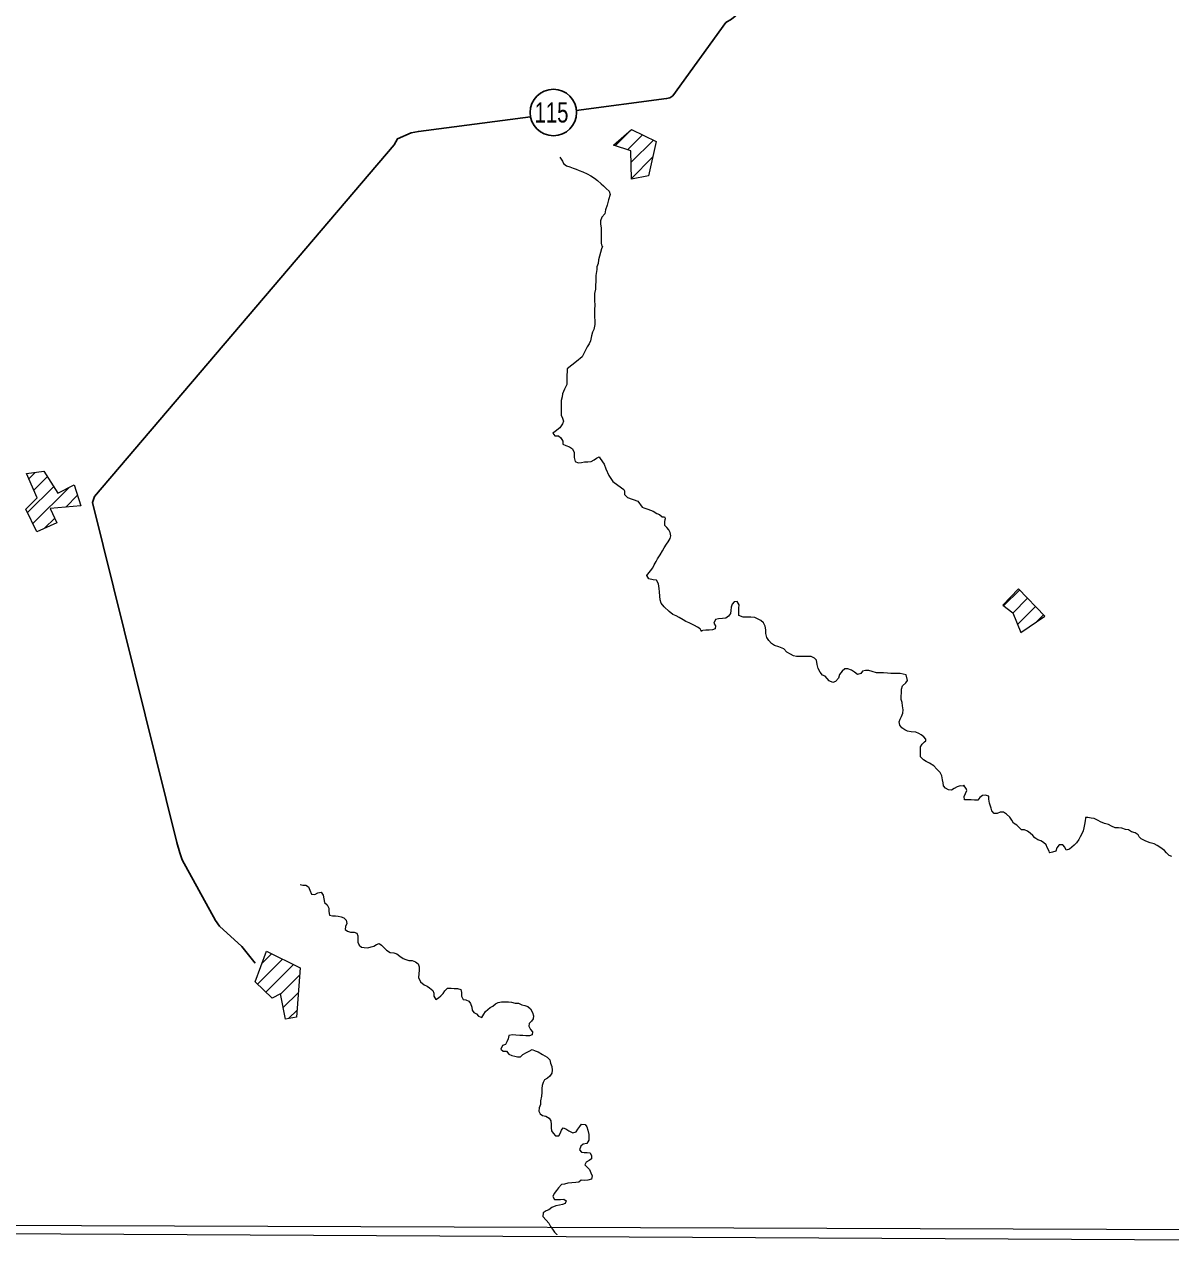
# Model space of a CAD drawing. Extents: x 553962 to 842807, y 8883888 to 9032388.
# Drawn here: x 611216 to 615180, y 8898711 to 8902976 of the extents above; entities that cross this region are included whole.
import ezdxf
from ezdxf.enums import TextEntityAlignment as Align

# ---------------------------------------------------------------- set-up
doc = ezdxf.new("R2010")
doc.units = 0
doc.header["$LTSCALE"] = 200
doc.layers.add('6', color=7, linetype='Continuous', lineweight=13)

msp = doc.modelspace()

# ---------------------------------------------------------------- linework, layer by layer
at = {"layer": '6'}
for p, q in [((613258.9, 8902557.5), (613307.3, 8902605.9)), ((613301.4, 8902543.4), (613353.5, 8902595.5)), ((613314.5, 8902500), (613391.6, 8902577)), ((613315.6, 8902444.5), (613388.7, 8902517.5)), ((611230.3, 8901404.8), (611252.2, 8901426.7)), ((611226.5, 8901287.9), (611316.8, 8901378.2)), ((611248, 8901365.9), (611294.8, 8901412.8)), ((611245.1, 8901249.9), (611370.1, 8901374.9)), ((611358.8, 8901307.1), (611399.5, 8901347.8)), ((611285.4, 8901233.7), (611320.5, 8901268.7)), ((614602.7, 8900965), (614658.4, 8901020.7)), ((614634.6, 8900940.2), (614686, 8900991.7)), ((614651.2, 8900900.4), (614713.6, 8900962.7)), ((614718.1, 8900910.6), (614741.2, 8900933.8)), ((613558.2, 8900878.2), (613557.9, 8900877)), ((612037, 8899727.6), (612070.7, 8899761.3)), ((612022, 8899656), (612108.6, 8899742.6)), ((612051.1, 8899628.6), (612146.6, 8899724)), ((612101.1, 8899622), (612167.9, 8899688.8)), ((612110.5, 8899574.8), (612163.2, 8899627.5)), ((612129.1, 8899536.8), (612158.5, 8899566.2))]:
    msp.add_line(p, q, dxfattribs=at)
for points in [[(618535.2, 8909853.3), (607574.3, 8909890.7), (607543.3, 8898835.3), (618504.2, 8898795.8)], [(613253.6, 8902559.2), (613316.1, 8902613.6), (613400.9, 8902572.5), (613374.3, 8902452.9), (613315.7, 8902442), (613313.8, 8902539.4)], [(611222.2, 8901422.7), (611283.2, 8901431), (611331.4, 8901355.2), (611388, 8901384.1), (611411, 8901311.7), (611304.4, 8901302.2), (611328.1, 8901252.8), (611258.8, 8901221.7), (611220.8, 8901299.8), (611260, 8901339.5)], [(614654.9, 8901024.3), (614599.9, 8900967.2), (614634.5, 8900940.5), (614662.7, 8900873), (614745.5, 8900929.3)], [(612052.6, 8899770.2), (612169.7, 8899712.7), (612156.6, 8899541.5), (612118.4, 8899535), (612101, 8899622.7), (612072.7, 8899608.2), (612013.7, 8899663.8)]]:
    msp.add_lwpolyline(points, close=True, dxfattribs=at)
at = {"layer": '6', "lineweight": 25}
for points in [[(614884.3, 8904031.6), (614289.5, 8903510.2), (613661, 8902994.8), (613641.6, 8902983.7), (613458.3, 8902730.3), (613448.1, 8902723.2), (613436.9, 8902720.2), (613124.7, 8902678.9)], [(612965.8, 8902657.9), (612578.6, 8902606.6), (612553.1, 8902601.6), (612506.2, 8902581.3), (612494.9, 8902560.9), (611458.3, 8901343.3), (611451.1, 8901322.9), (611742.2, 8900146.7), (611753.3, 8900110), (611761.3, 8900086.6), (611876.7, 8899876.5), (611889.9, 8899857.1), (611968.1, 8899786.6), (612014.2, 8899728.6)]]:
    msp.add_lwpolyline(points, dxfattribs=at)
at = {"layer": '6'}
for points in [[(613067.8, 8902517.8), (613076.8, 8902504.5), (613080.8, 8902495.3), (613091, 8902488.1), (613102.1, 8902483.9), (613113.3, 8902479.8), (613124.5, 8902476.7), (613134.6, 8902471.5), (613147.8, 8902467.4), (613162, 8902460.2), (613175.2, 8902452.9), (613187.3, 8902444.7), (613197.4, 8902436.5), (613210.6, 8902425.2), (613218.7, 8902418.1), (613227.7, 8902409.8), (613238.9, 8902399.6), (613241.8, 8902388.4), (613236.6, 8902370.1), (613231.4, 8902351.8), (613226.2, 8902335.5), (613223.1, 8902321.3), (613212.8, 8902310.1), (613208.7, 8902296.9), (613208.6, 8902286.7), (613210.5, 8902272.5), (613210.5, 8902262.3), (613210.3, 8902245), (613210.2, 8902232.7), (613210.2, 8902220.5), (613213.1, 8902210.3), (613215.1, 8902208.5)], [(613214.9, 8902208.8), (613211.4, 8902200.8), (613205.1, 8902175.3), (613200.9, 8902162.1), (613199.8, 8902149.9), (613195.7, 8902138.7), (613195.6, 8902128.6), (613192.4, 8902108.2), (613192.3, 8902087.8), (613191.2, 8902074.6), (613191.1, 8902061.3), (613187.9, 8902046.1), (613187.8, 8902034.9), (613187.8, 8902023.7), (613188.9, 8902003.7), (613187.6, 8901993.1), (613187.5, 8901980.9), (613187.4, 8901965.6), (613188.3, 8901951.4), (613189.2, 8901939.2), (613185.5, 8901921), (613180.9, 8901911.7), (613176.7, 8901899.5), (613173.6, 8901882.2), (613169.4, 8901872.1), (613162.2, 8901861.9), (613144.8, 8901826.3), (613125.2, 8901810.6), (613093.6, 8901785.9), (613093.5, 8901775.8), (613092.4, 8901763.5), (613092.3, 8901753.4), (613092.2, 8901743.2), (613092.2, 8901730.9), (613083.9, 8901714.7), (613076.7, 8901698.5), (613075.6, 8901688.3), (613072.5, 8901676.1), (613072.4, 8901663.9), (613072.2, 8901647.6), (613072.2, 8901635.3), (613072.1, 8901625.2), (613077.1, 8901614.9), (613080.1, 8901604.7), (613077, 8901594.6), (613067.7, 8901581.4), (613051.4, 8901568.2), (613043.2, 8901562.2), (613050.2, 8901554), (613062.5, 8901553.9), (613071.6, 8901546.7), (613077.6, 8901534.5), (613078.5, 8901524.3), (613088.7, 8901520.2), (613100.8, 8901515), (613111, 8901508.8), (613117, 8901495.5), (613116.8, 8901478.2), (613120.8, 8901464.9), (613131, 8901459.8), (613143.2, 8901460.7), (613153.4, 8901463.7), (613164.6, 8901463.7), (613175.8, 8901464.6), (613186, 8901470.7), (613194.2, 8901476.7), (613203.3, 8901480.7)], [(613203.3, 8901480.7), (613207.5, 8901475.3), (613220.8, 8901455), (613227, 8901438.8), (613237.3, 8901416.4), (613250.6, 8901395.1), (613268, 8901382.9), (613288.8, 8901367.7)], [(613288.8, 8901367.7), (613291.1, 8901363.5), (613291.6, 8901350.4), (613301.8, 8901340.3), (613337.5, 8901327.3), (613352.9, 8901307), (613358, 8901304), (613372.2, 8901300), (613390.6, 8901292.9), (613402.8, 8901284.9)], [(613369.1, 8901070.7), (613389.4, 8901097.2), (613393.5, 8901107.3), (613400.7, 8901118.5), (613405.9, 8901127.6), (613415.1, 8901141.8), (613422.3, 8901156.1), (613428.5, 8901166.2), (613436.8, 8901178.4), (613442.9, 8901186.5), (613449.1, 8901197.7), (613452.2, 8901207.8), (613449.2, 8901219), (613444.2, 8901228.2), (613438.2, 8901236.4), (613431.1, 8901243.6), (613431.2, 8901254.8), (613432.3, 8901265), (613432.3, 8901265)], [(613402.8, 8901284.9), (613412.2, 8901280.8), (613421.3, 8901273.6), (613429.4, 8901273), (613432.2, 8901268.8), (613432.3, 8901265)], [(613557.9, 8900877), (613552.9, 8900886.2), (613543.8, 8900891.3), (613533.6, 8900897.5), (613524.5, 8900901.7), (613515.4, 8900906.8), (613503.2, 8900910.9), (613494.1, 8900917.1), (613480.9, 8900925.3), (613469.8, 8900930.5), (613458.6, 8900934.7), (613445.5, 8900945.9), (613428.3, 8900962.3), (613418.2, 8900974.6), (613415.3, 8900985.9), (613413.3, 8900999.1), (613412.4, 8901013.4), (613411.5, 8901025.6), (613408.5, 8901040.9), (613401.5, 8901054.2), (613390.3, 8901055.3), (613375.1, 8901058.4), (613369.1, 8901070.7), (613369.1, 8901072), (613369.1, 8901070.7)], [(614265.5, 8900726.8), (614255.3, 8900728.9), (614245.2, 8900731), (614233, 8900731.1), (614222.8, 8900731.2), (614212.6, 8900731.2), (614201.5, 8900732.3), (614187.2, 8900733.4), (614174, 8900733.5), (614162.8, 8900733.6), (614148.6, 8900737.8), (614136.4, 8900741.9), (614125.2, 8900742), (614115.1, 8900739), (614108.9, 8900730.9), (614097.7, 8900727.9), (614086.6, 8900736.1), (614076.4, 8900742.3), (614064.3, 8900747.5), (614054.1, 8900747.5), (614044.9, 8900739.4), (614034.6, 8900727.3), (614031.5, 8900715.1), (614021.2, 8900703.9), (614012.1, 8900699.9), (613999.9, 8900706.1), (613992.8, 8900714.3), (613985.8, 8900721.5), (613976.6, 8900725.6), (613968.6, 8900735.8), (613961.5, 8900748.1), (613957.6, 8900762.4), (613955.6, 8900776.7), (613948.6, 8900783.8), (613937.4, 8900790), (613924.2, 8900790.1), (613914, 8900790.2), (613899.8, 8900790.3), (613886.6, 8900790.3), (613876.4, 8900792.4), (613865.3, 8900797.6), (613853.1, 8900804.8), (613843, 8900816.1), (613824.8, 8900823.3), (613810.6, 8900827.5), (613799.4, 8900834.7), (613790.3, 8900844.9), (613783.3, 8900856.2), (613780.3, 8900869.4), (613780.4, 8900882.7), (613777.5, 8900894.9), (613772.5, 8900906.2), (613763.4, 8900914.4), (613751.2, 8900920.6), (613742.1, 8900924.7), (613728.9, 8900925.8), (613714.6, 8900925.9), (613701.4, 8900926), (613687.2, 8900932.2), (613687.3, 8900944.4), (613687.4, 8900957.6), (613687.5, 8900968.8), (613681.5, 8900980.1), (613671.3, 8900979.1), (613664.1, 8900971), (613660, 8900960.8), (613658.9, 8900948.6), (613657.8, 8900938.5), (613650.6, 8900929.3), (613641.4, 8900922.3), (613630.2, 8900921.3), (613617, 8900920.4), (613605.8, 8900917.4), (613600.6, 8900905.2), (613605.6, 8900896), (613604.5, 8900885.8), (613595.3, 8900881.8), (613584.1, 8900880.9), (613573, 8900880.9), (613562.8, 8900880), (613558.2, 8900878.2)], [(614333.4, 8900497.8), (614333.4, 8900503.9), (614326.3, 8900512.1), (614318.2, 8900518.3), (614309.1, 8900523.4), (614299, 8900528.6), (614282.7, 8900528.7), (614270.5, 8900531.8), (614261.4, 8900535.9), (614251.3, 8900543.1), (614244.2, 8900552.3), (614241.2, 8900563.6), (614245.4, 8900572.7), (614249.5, 8900581.8), (614254.7, 8900594), (614254.8, 8900605.2), (614252.8, 8900619.5), (614251.9, 8900630.7), (614247.9, 8900640.9), (614248, 8900652.1), (614249.1, 8900664.3), (614249.2, 8900676.6), (614253.3, 8900688.8), (614264.6, 8900698.9), (614270.7, 8900707), (614265.5, 8900726.8)], [(614664.7, 8900190.6), (614656.6, 8900197.8), (614648.6, 8900206), (614637.4, 8900213.2), (614631.4, 8900223.4), (614624.3, 8900233.6), (614613.2, 8900243.9), (614602.1, 8900251.1), (614590.9, 8900251.2), (614580.7, 8900247.2), (614570.5, 8900247.2), (614562.5, 8900255.4), (614559.5, 8900265.6), (614553.5, 8900281.9), (614551.6, 8900296.2), (614551.6, 8900306.4), (614539.4, 8900310.6), (614529.3, 8900308.6), (614521.1, 8900301.5), (614513.9, 8900292.4), (614502.7, 8900292.5), (614490.5, 8900293.6), (614480.3, 8900293.6), (614468.1, 8900293.7), (614466.2, 8900305.9), (614471.3, 8900316.1), (614475.5, 8900326.2), (614473.7, 8900333.3), (614468.3, 8900338.8), (614465.5, 8900344.2), (614462.8, 8900341.5), (614452.2, 8900342.7), (614442, 8900338.7), (614431.8, 8900332.6), (614422.6, 8900327.6), (614412.4, 8900328.7), (614402.3, 8900333.8), (614395.2, 8900342), (614394.3, 8900352.2), (614391.3, 8900363.4), (614389.4, 8900376.7), (614383.4, 8900388.9), (614372.3, 8900400.2), (614361.2, 8900411.5), (614347, 8900420.8), (614334.8, 8900426.9), (614325.7, 8900432.1), (614315.6, 8900442.3), (614315.7, 8900454.6), (614315.8, 8900464.7), (614315.8, 8900477), (614321, 8900486.1), (614329.2, 8900495.2), (614333.4, 8900497.8)], [(614885.7, 8900232.8), (614885.7, 8900230.9), (614884.6, 8900220.8), (614882.5, 8900208.6), (614880.4, 8900197.4), (614878.3, 8900187.2), (614874.1, 8900178.1), (614867.9, 8900165.9), (614862.8, 8900156.8), (614854.6, 8900144.6), (614847.4, 8900137.5), (614839.2, 8900130.4), (614831, 8900123.3), (614819.8, 8900119.3), (614814.8, 8900130.6), (614807.7, 8900137.8), (614794.5, 8900138.8), (614787.3, 8900127.7), (614783.2, 8900116.5), (614772, 8900112.5), (614762.4, 8900110.6), (614761.4, 8900112.2)], [(614976, 8900202.9), (614965.9, 8900209.1), (614951.7, 8900212.2), (614938.5, 8900217.4), (614929.4, 8900222.5), (614916.2, 8900229.7), (614906, 8900230.8), (614893.8, 8900232.9), (614885.7, 8900233), (614885.7, 8900232.8)], [(614761.4, 8900112.2), (614760.8, 8900116.7), (614753.8, 8900128.9), (614749.8, 8900138.1), (614740.7, 8900146.3), (614731.6, 8900151.5), (614721.4, 8900155.6), (614710.3, 8900162.8), (614704.2, 8900171), (614695.1, 8900178.2), (614686, 8900185.4), (614674.9, 8900190.5), (614664.7, 8900190.6)], [(615185.3, 8900097.6), (615176.1, 8900101.7), (615166, 8900110.9), (615159, 8900118.1), (615143.8, 8900130.4), (615133.7, 8900135.6), (615123.5, 8900141.8), (615110.3, 8900145.6), (615095.2, 8900150.4), (615078.5, 8900159.2), (615071.3, 8900166.3), (615068.1, 8900172.7), (615057.7, 8900179.9), (615045.5, 8900183), (615034.4, 8900190.2), (615024.2, 8900191.3), (615012, 8900195.4), (614999.8, 8900196.5), (614988.7, 8900197.6), (614976, 8900202.9)], [(612169.4, 8900000.7), (612179.1, 8899998.2), (612189.2, 8899998.2), (612198.4, 8899993), (612202.4, 8899980.8), (612208.4, 8899967.5), (612220.6, 8899966.4), (612230.8, 8899972.4), (612242, 8899974.4), (612249, 8899964.2), (612251, 8899951.9), (612254, 8899938.7), (612263.1, 8899930.5), (612269.1, 8899919.2), (612269, 8899907), (612270.9, 8899894.8), (612281.1, 8899892.7), (612291.3, 8899892.6), (612301.4, 8899891.5), (612311.6, 8899889.4), (612320.7, 8899885.3), (612328.8, 8899877.1), (612330.8, 8899865.9), (612326.6, 8899855.7), (612325.5, 8899845.5), (612333.6, 8899839.3), (612343.8, 8899836.2), (612356, 8899836.2), (612365.1, 8899832), (612369.1, 8899822.8), (612369.1, 8899812.6), (612369, 8899801.4), (612374, 8899791.2), (612381.1, 8899784), (612391.2, 8899782.9), (612403.4, 8899781.8), (612414.6, 8899784.8), (612424.8, 8899787.8), (612433, 8899793.9), (612443.2, 8899796.9), (612451.3, 8899790.7), (612458.4, 8899782.5), (612468.5, 8899773.3), (612480.6, 8899765.1), (612493.8, 8899765), (612504, 8899760.8), (612514.1, 8899752.6), (612526.2, 8899745.4), (612535.4, 8899741.3), (612545.5, 8899738.2), (612556.7, 8899738.1), (612567.9, 8899733.9), (612578, 8899726.7), (612581, 8899716.5), (612580.9, 8899704.3), (612579.8, 8899692.1), (612578.7, 8899678.8), (612585.7, 8899664.5), (612597.8, 8899654.3), (612609, 8899649.1), (612617.1, 8899642.9), (612628.2, 8899634.7), (612632.2, 8899625.5), (612632.2, 8899614.3), (612638.2, 8899603.1), (612648.4, 8899609.1), (612655.6, 8899616.2), (612663.8, 8899623.3), (612669.9, 8899633.4), (612679.2, 8899642.6), (612691.4, 8899642.5), (612702.5, 8899641.4), (612713.7, 8899641.3), (612724.9, 8899637.2), (612727.9, 8899626.9), (612727.8, 8899614.7), (612732.8, 8899602.5), (612743, 8899602.4), (612753.1, 8899597.2), (612759.1, 8899589.1), (612763.1, 8899576.8), (612764.1, 8899566.6), (612770.1, 8899558.4), (612779.2, 8899553.3), (612786.3, 8899545.1), (612797.5, 8899540.9), (612804.7, 8899552.1), (612810.8, 8899561.2), (612819, 8899568.3), (612826.2, 8899575.4), (612836.4, 8899580.4), (612844.6, 8899587.5), (612854.8, 8899592.5), (612866, 8899595.5), (612877.2, 8899595.4), (612890.4, 8899595.3), (612900.6, 8899594.3), (612912.8, 8899590.1), (612925, 8899590), (612936.1, 8899584.9), (612946.3, 8899581.8)], [(612946.3, 8899581.8), (612957.4, 8899578.6), (612966.5, 8899570.4), (612972.6, 8899558.2), (612976.5, 8899546.9), (612975.5, 8899535.7), (612969.3, 8899527.6), (612962.1, 8899520.5), (612961, 8899510.3), (612966, 8899499.1), (612973.1, 8899490.9), (612971.8, 8899480.8), (612962.8, 8899477.7), (612950.6, 8899477.8), (612939.5, 8899477.9), (612929.3, 8899477.9), (612915.1, 8899480.1), (612903.9, 8899481.2), (612891.6, 8899478.2), (612888.5, 8899467), (612884.4, 8899456.8), (612880.2, 8899447.7), (612869, 8899443.7), (612863.8, 8899431.5), (612871.9, 8899424.3), (612883.1, 8899424.2), (612891.2, 8899414), (612901.3, 8899408.8), (612911.5, 8899406.7), (612921.7, 8899404.6), (612931.8, 8899404.6), (612940, 8899412.7), (612952.3, 8899419.7), (612961.5, 8899424.8), (612971.7, 8899429.8), (612981.8, 8899425.7), (612993, 8899422.5), (613007.2, 8899412.2), (613024.4, 8899403), (613033.5, 8899394.8), (613035.4, 8899382.5), (613040.4, 8899371.3), (613041.4, 8899358), (613040.3, 8899347.8), (613033.1, 8899337.7), (613024.9, 8899330.6), (613014.7, 8899324.6), (613009.5, 8899315.4), (613006.4, 8899305.3), (613005.3, 8899295.1), (613005.2, 8899280.8), (613004.1, 8899268.6), (613001, 8899252.3), (613000.9, 8899240.1), (612995.7, 8899227.9), (612994.6, 8899216.7), (612999.6, 8899207.5), (613007.7, 8899201.3), (613018.9, 8899199.2), (613031.1, 8899192), (613036.1, 8899182.8), (613038, 8899170.6), (613038, 8899158.4), (613038.9, 8899148.2), (613045, 8899140), (613053, 8899130.8), (613064.2, 8899130.7), (613069.4, 8899139.8), (613073.5, 8899151), (613079.7, 8899159.1), (613088.8, 8899155), (613098.9, 8899148.8), (613112.1, 8899141.6), (613124.3, 8899145.6), (613130.5, 8899154.7), (613136.7, 8899163.8), (613142.8, 8899172), (613155, 8899170.9), (613161.1, 8899162.7), (613165.1, 8899151.4), (613168, 8899136.1), (613167.9, 8899125.9), (613167.9, 8899115.8), (613160.7, 8899104.6), (613148.5, 8899102.7), (613140.3, 8899095.6), (613136.1, 8899083.4), (613142.2, 8899075.2), (613152.3, 8899074.1), (613162.5, 8899074), (613172.7, 8899072.9), (613176.7, 8899061.7), (613177.6, 8899051.5), (613169.4, 8899045.5), (613158.2, 8899040.4), (613154.1, 8899031.3), (613161.1, 8899024.1), (613170.2, 8899014.9), (613175.2, 8899003.7), (613179.2, 8898992.4), (613177.1, 8898981.2)], [(574695.3, 8898953.2), (596544.3, 8898870.4), (626625.7, 8898710.8)], [(613177.1, 8898981.2), (613164.9, 8898978.2), (613152.7, 8898976.3), (613141.5, 8898978.4), (613133.3, 8898971.3), (613123.1, 8898969.3), (613108.9, 8898968.4), (613095.6, 8898967.5), (613083.4, 8898963.5), (613073.2, 8898962.5), (613063, 8898951.4), (613055.8, 8898942.3), (613047.6, 8898932.1), (613043.5, 8898921), (613049.5, 8898910.7), (613059.7, 8898910.7), (613069.8, 8898910.6), (613081, 8898911.6), (613090.1, 8898906.4), (613086, 8898897.2), (613076.8, 8898893.2), (613066.6, 8898891.3), (613054.4, 8898889.3), (613040.1, 8898883.3), (613029.9, 8898875.2), (613020.7, 8898871.2), (613009.5, 8898865.2), (613008.4, 8898851.9), (613020.5, 8898839.6), (613029.6, 8898829.4), (613035.6, 8898818.1), (613042.7, 8898807.9), (613048.7, 8898797.7), (613056.8, 8898789.4), (613057.8, 8898788.4)]]:
    msp.add_lwpolyline(points, dxfattribs=at)
at = {"layer": '6', "lineweight": 25}
msp.add_circle((613045.3, 8902672.4), 80.3, dxfattribs=at)

# ---------------------------------------------------------------- texts
at = {"layer": '6', "width": 0.75}
msp.add_text('115', height=70, dxfattribs=at).set_placement((613038.9, 8902637.7), align=Align.CENTER)

doc.saveas('drawing.dxf')
